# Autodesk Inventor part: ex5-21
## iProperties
Created: 2006-03
Part Number: ex5-21
Document SubType Name: Modeling
Designer: Elise Moss
Author: Elise Moss
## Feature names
1. Extrusion1
2. Hole1
3. Hole2
4. Key Square (Hole)1 [Extrusion]
